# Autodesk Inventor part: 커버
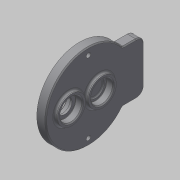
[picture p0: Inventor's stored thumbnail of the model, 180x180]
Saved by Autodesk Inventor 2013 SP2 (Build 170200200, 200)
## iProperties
Created: 2016-02
Part Number: 커버
Material: 일반
Document SubType Name: Modeling
Designer: mduedu
Density: 1 g/cm^3
Author: mduedu
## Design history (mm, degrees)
sketch "스케치1"
  geometry: C1 r 43 at (0, 0); 1 further point
  constraints: 1 centre point, 1 coincident
  dimensions: "d0" = 86 diameter of C1
extrude "돌출1" new body sketch "스케치1" distance "d1" = 9; taper "d2" = 0 deg
sketch "스케치2"
  geometry: C1 r 14 at (0, 11); 1 further point
  constraints: 1 centre point, 1 vertical alignment
  dimensions: "d3" = 28 diameter of C1; "d6" = 11 distance of C1.centre point (0, 0)
extrude "돌출2" join sketch "스케치2" distance "d7" = 3; taper "d8" = 0 deg
sketch "스케치3"
  geometry: C1 r 14 at (0, -20); 1 further point
  constraints: 1 centre point, 1 vertical alignment
  dimensions: "d9" = 28 diameter of C1; "d10" = 20 distance of C1.centre point (0, 0)
extrude "돌출3" join sketch "스케치3" distance "d11" = 3; taper "d12" = 0 deg
hole "구멍1" diameter "d15" = 22; stored, may be unused: countersink angle "d19" = 90 deg, drill point angle "d21" = 0 deg; dims "d13" = 10, "d14" = 10, "d16" = 6, "d17" = 4, "d18" = 2, "d20" = 7
hole "구멍2" diameter "d24" = 18; stored, may be unused: countersink angle "d28" = 90 deg, drill point angle "d30" = 0 deg; dims "d22" = 10, "d23" = 10, "d25" = 6, "d26" = 4, "d27" = 2, "d29" = 1
hole "구멍3" diameter "d33" = 22; stored, may be unused: countersink angle "d37" = 90 deg, drill point angle "d39" = 0 deg; dims "d34" = 6, "d35" = 4, "d36" = 2, "d38" = 7, "d73" = 10, "d74" = 10
sketch "스케치7"
  geometry: L1 (-26, 34.249)-(26, 34.249); L2 (26, 34.249)-(26, 56); L3 (26, 56)-(-26, 56); L4 (-26, 56)-(-26, 34.249); A1 r 43 centre (0, 0) between (-26, 34.249) and (26, 34.249) reference; 1 further point
  constraints: 8 end point, 2 parallel, 2 point on circle, 1 horizontal, 1 perpendicular
  dimensions: "d95" = 52 distance of L2.end L3.end; "d97" = 56 distance from line of L3 point (0, 0)
extrude "돌출5" join sketch "스케치7" stored distance "d98" = 10; taper "d99" = 0 deg
sketch "스케치4"
  geometry: C1 r 14 at (0, -20) reference; C2 r 18 at (0, -20); 1 further point
  constraints: 1 centre point, 1 coincident
  dimensions: "d40" = 36 diameter of C2
extrude "돌출4" join sketch "스케치4" distance "d41" = 4; taper "d42" = 0 deg
hole "구멍4" diameter "d45" = 22; stored, may be unused: countersink angle "d49" = 90 deg, drill point angle "d51" = 0 deg; dims "d43" = 10, "d44" = 10, "d46" = 6, "d47" = 4, "d48" = 2, "d50" = 7
hole "구멍5" diameter "d54" = 15; stored, may be unused: countersink angle "d58" = 90 deg, drill point angle "d60" = 0 deg; dims "d52" = 10, "d53" = 10, "d55" = 6, "d56" = 4, "d57" = 2, "d59" = 7
fillet "모깎기1" dims "d61" = 0.3
fillet "모깎기2" dims "d62" = 2
chamfer "모따기1" distance "d63" = 1; stored, may be unused: second distance "d64" = 2, angle "d65" = 45 deg
fillet "모깎기6" dims "d88" = 2
sketch "스케치5" dims "d67" = 72
  geometry: 4 further points
  constraints: 2 horizontal alignment, 1 coincident, 5 other
  dimensions: "d71" = 360 deg dimension on point (0, 0) point (-36, 0) (derived)
fillet "모깎기4" dims "d75" = 2
sketch "스케치6"
  geometry: 2 further points
hole "구멍6" sketch "스케치6" at (36, 0), (-36, 0) diameter "d76" = 4.5; stored, may be unused: countersink angle "d80" = 90 deg, drill point angle "d82" = 0 deg; dims "d77" = 6, "d78" = 8, "d79" = 4.6, "d81" = 8
fillet "모깎기7" dims "d100" = 8, "d101" = 2
chamfer "모따기2" distance "d90" = 1; stored, may be unused: second distance "d91" = 2, angle "d92" = 45 deg
node "솔리드1"
node "절단 모서리 투영1"
